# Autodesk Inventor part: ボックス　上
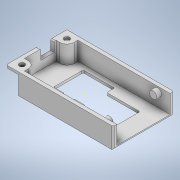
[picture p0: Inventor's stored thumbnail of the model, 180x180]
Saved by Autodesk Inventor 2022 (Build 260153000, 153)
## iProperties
Created: 2024-12
Part Number: ボックス　上
Material: 一般
Document SubType Name: Modeling
Designer: jsat7
Density: 1 g/cm^3
Appearance: 既定
Author: jsat7
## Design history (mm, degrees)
sketch "スケッチ1"
  geometry: L1 (19.188, -11.63)-(-24.812, -11.63); L2 (-24.812, -11.63)-(-24.812, 13.37); L3 (-24.812, 13.37)-(19.188, 13.37); L4 (19.188, 13.37)-(19.188, -11.63); 1 further point
  constraints: 8 end point, 2 parallel, 1 horizontal, 1 perpendicular
  dimensions: "d0" = 44 distance of L1.start L1.end; "d1" = 25 distance of L3.end L1.start
extrude "押し出し1" new body sketch "スケッチ1" distance "d2" = 1; taper "d3" = 0 deg
sketch "スケッチ2"
  geometry: L1 (-13.188, 10.13)-(24.812, 10.13); L2 (24.812, -11.87)-(-13.188, -11.87); L3 (-13.188, -11.87)-(-13.188, 10.13); L4 (24.812, 11.63)-(-19.188, 11.63) reference; L5 (-19.188, -13.37)-(24.812, -13.37) reference; L6 (-19.188, 11.63)-(-19.188, -13.37) reference; L7 (24.812, -13.37)-(24.812, 11.63) reference; 3 further points
  constraints: 6 end point, 1 horizontal, 1 parallel
  dimensions: "d4" = 1.5 distance between parallel lines of L1 L4; "d5" = 1.5 distance between parallel lines of L5 L2; "d6" = 6 distance between parallel lines of L6 L3
extrude "押し出し2" join sketch "スケッチ2" distance "d8" = 7.5; taper "d9" = 0 deg
sketch "スケッチ3"
  geometry: L1 (-13.188, -11.87)-(-13.188, 10.13) reference; L2 (-13.188, 5.63)-(-17.688, 5.63); L3 (-17.688, 5.63)-(-17.688, -7.37); L4 (-17.688, -7.37)-(-13.188, -7.37); L5 (-13.188, -7.37)-(-13.188, 5.63); L6 (24.812, 11.63)-(-19.188, 11.63) reference; L7 (-19.188, -13.37)-(24.812, -13.37) reference; L8 (-19.188, 11.63)-(-19.188, -13.37) reference; 2 further points
  constraints: 8 end point, 2 parallel, 1 horizontal, 1 perpendicular, 1 point on line
  dimensions: "d10" = 6 distance between parallel lines of L6 L2; "d11" = 6 distance between parallel lines of L7 L4; "d12" = 1.5 distance between parallel lines of L8 L3
extrude "押し出し3" cut sketch "スケッチ3" distance "d13" = 7.5; taper "d14" = 0 deg
fillet "フィレット1" dims "d15" = 3
fillet "フィレット2" dims "d16" = 3
sketch "スケッチ4"
  geometry: L1 (-19.188, -11.63)-(-19.188, 13.37) reference; L2 (-19.188, -11.63)-(-14.188, -11.63); L3 (-14.188, -11.63)-(-14.188, -6.63); L4 (-14.188, -6.63)-(-19.188, -6.63); L5 (-19.188, -6.63)-(-19.188, -11.63); L6 (-19.188, 13.37)-(-14.188, 13.37); L7 (-14.188, 13.37)-(-14.188, 8.37); L8 (-14.188, 8.37)-(-19.188, 8.37); L9 (-19.188, 8.37)-(-19.188, 13.37); 3 further points
  constraints: 16 end point, 4 parallel, 2 horizontal, 2 perpendicular
  dimensions: "d17" = 5 distance of L7.end L8.end; "d18" = 5 distance of L6.end L7.end; "d19" = 5 distance of L3.end L4.end; "d20" = 5 distance of L2.end L3.end
extrude "押し出し4" cut sketch "スケッチ4" distance "d21" = 7.5; taper "d22" = 0 deg
fillet "フィレット3" dims "d23" = 2
fillet "フィレット4" dims "d24" = 2
sketch "スケッチ5"
  geometry: L1 (38, 0)-(38, 7.5) reference; L2 (0, 7.5)-(38, 7.5) reference; C1 r 1.5 at (33, 5.5); 1 further point
  constraints: 1 centre point
  dimensions: "d25" = 5 distance from line of L1 C1.centre; "d26" = 2 distance from line of L2 C1.centre; "d27" = 3 diameter of C1
extrude "押し出し5" join sketch "スケッチ5" distance "d28" = 2; taper "d29" = 0 deg
sketch "スケッチ6"
  geometry: L1 (0, 0)-(0, 7.5) reference; L2 (0, 7.5)-(38, 7.5) reference; C1 r 1.5 at (5, 5.5); 1 further point
  constraints: 1 centre point
  dimensions: "d30" = 5 distance from line of L1 C1.centre; "d31" = 2 distance from line of L2 C1.centre; "d32" = 3 diameter of C1
extrude "押し出し6" join sketch "スケッチ6" distance "d33" = 2; taper "d34" = 0 deg
sketch "スケッチ7"
  geometry: L1 (24.812, 11.63)-(-19.188, 11.63) reference; L2 (-19.188, 11.63)-(-19.188, -13.37) reference; L3 (-19.188, -13.37)-(24.812, -13.37) reference; C1 r 1.1 at (-15.938, -10.12); C2 r 1.1 at (-15.938, 8.38); 1 further point
  constraints: 2 centre point
  dimensions: "d35" = 3.25 distance from line of L1 C2.centre; "d36" = 3.25 distance from line of L2 C2.centre; "d37" = 3.25 distance from line of L2 C1.centre; "d38" = 3.25 distance from line of L3 C1.centre; "d39" = 2.2 diameter of C1; "d40" = 2.2 diameter of C2
extrude "押し出し7" cut sketch "スケッチ7" distance "d41" = 12; taper "d42" = 0 deg
sketch "スケッチ8"
  geometry: 1 further point
sketch "スケッチ10"
  geometry: L1 (19, 0)-(6, 0) reference; L2 (6.7, 0)-(12.2, 0); L3 (12.2, 0)-(12.2, -4); L4 (12.2, -4)-(6.7, -4); L5 (6.7, -4)-(6.7, 0); L6 (0, -8.5)-(0, -1) reference; 2 further points
  constraints: 8 end point, 2 parallel, 1 horizontal, 1 perpendicular, 1 point on line
  dimensions: "d43" = 6.7 distance between parallel lines of L5 L6; "d44" = 5.5 distance between parallel lines of L3 L5; "d45" = 4 distance between parallel lines of L1 L4
extrude "押し出し8" cut sketch "スケッチ10" distance "d46" = 1.5; taper "d47" = 0 deg
fillet "フィレット5" dims "d48" = 0.5
fillet "フィレット6" dims "d49" = 0.5
sketch "スケッチ11"
  geometry: L1 (3.912, 6.77)-(17.612, 6.77); L2 (17.612, 6.77)-(17.612, -4.93); L3 (17.612, -4.93)-(3.912, -4.93); L4 (3.912, -4.93)-(3.912, 6.77); L5 (24.812, 13.37)-(24.812, -11.63) reference; L6 (-14.188, 13.37)-(24.812, 13.37) reference; L7 (3.912, 4.07)-(-8.988, 4.07); L8 (-8.988, 4.07)-(-8.988, -8.13); L9 (-8.988, -8.13)-(3.912, -8.13); L10 (3.912, -8.13)-(3.912, 4.07); L11 (-19.188, -6.63)-(-19.188, 8.37) reference; L12 (24.812, -11.63)-(-14.188, -11.63) reference; A1 r 2.25 centre (-2.538, 4.07) between (-0.288, 4.07) and (-4.788, 4.07); A2 r 2.25 centre (9.166, 6.77) between (11.416, 6.77) and (6.916, 6.77); 2 further points
  constraints: 16 end point, 6 point on line, 4 parallel, 4 point on circle, 2 centre point, 2 horizontal, 2 perpendicular, 1 midpoint
  dimensions: "d50" = 7.2 distance between parallel lines of L5 L2; "d51" = 6.6 distance between parallel lines of L6 L1; "d52" = 13.7 distance of L1.start L1.end; "d53" = 11.7 distance of L1.end L2.end; "d54" = 9.3 distance between parallel lines of L6 L7; "d55" = 10.2 distance between parallel lines of L11 L8; "d56" = 3.5 distance between parallel lines of L12 L9; "d57" = 4.5 diameter of A1; "d58" = 4.5 diameter of A2
extrude "押し出し9" cut sketch "スケッチ11" distance "d59" = 1.5; taper "d60" = 0 deg
fillet "フィレット7" dims "d61" = 0.5
chamfer "面取り1" distance "d62" = 0.5; stored, may be unused: second distance "d63" = 2, angle "d64" = 45 deg
chamfer "面取り2" distance "d65" = 0.5; stored, may be unused: second distance "d66" = 2, angle "d67" = 45 deg
chamfer "面取り3" distance "d68" = 0.5; stored, may be unused: second distance "d69" = 2, angle "d70" = 45 deg
node "ソリッド1"
